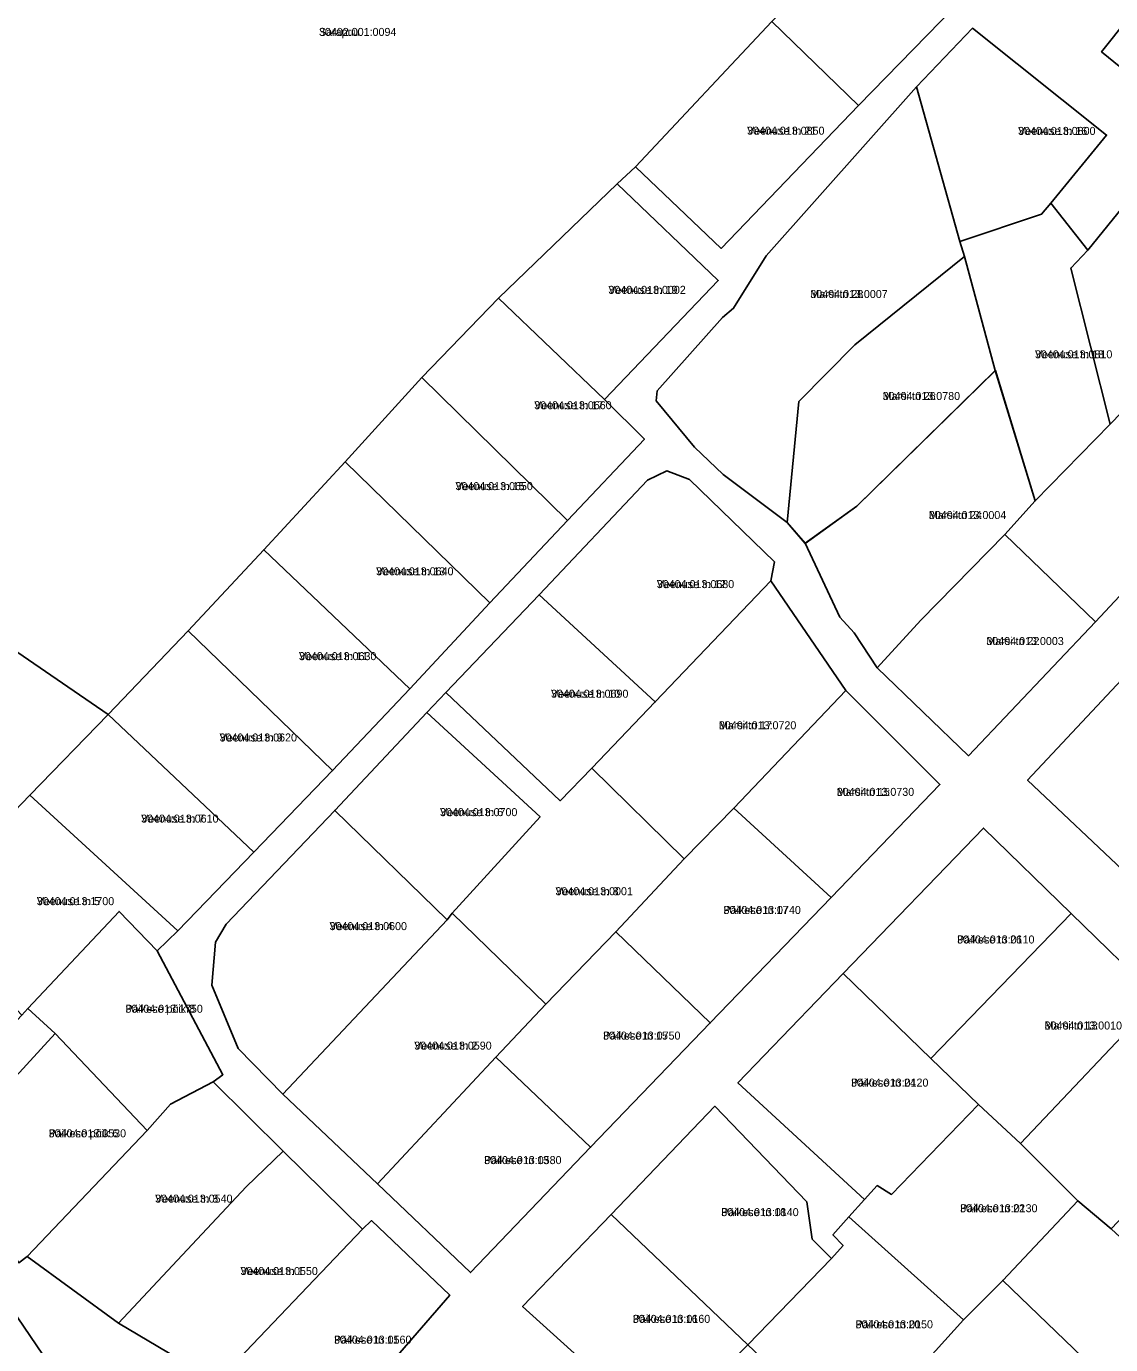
# Model space of a CAD drawing. Extents: x 542681 to 554572, y 6566489 to 6580482.
# Drawn here: x 543606.8 to 543809.9, y 6575908.9 to 6576155.9 of the extents above; entities that cross this region are included whole.
import ezdxf

# ---------------------------------------------------------------- set-up
doc = ezdxf.new("R2010")
doc.units = 0
for name, color, linetype in [('L_AADRESS', 7, 'Continuous'), ('PIIR', 7, 'Continuous'), ('TUNNUS', 7, 'Continuous')]:
    doc.layers.add(name, color=color, linetype=linetype)

msp = doc.modelspace()

# ---------------------------------------------------------------- linework, layer by layer
at = {"layer": 'PIIR'}
for points in [[(543610.08, 6576200.08), (543678.38, 6576251.99), (543771.59, 6576182.76), (543746.47, 6576156.82), (543720.94, 6576129.63), (543717.45, 6576126.42), (543695.26, 6576105.01), (543680.88, 6576090.14), (543666.51, 6576074.33), (543651.27, 6576057.86), (543637.1, 6576042.64), (543622.09, 6576026.97), (543551.63, 6576075.36)], [(543746.47, 6576156.82), (543771.59, 6576182.76), (543788.33, 6576167.45), (543762.71, 6576141.11)], [(543822.78, 6576169.45), (543851.24, 6576147.66), (543835.23, 6576129.22), (543808.25, 6576151.17)], [(543746.47, 6576156.82), (543762.71, 6576141.11), (543736.97, 6576114.33), (543720.94, 6576129.63)], [(543766.21, 6576035.75), (543783.28, 6576019.27), (543807.09, 6576044.34), (543831.37, 6576070.35), (543854.66, 6576098.47), (543838.99, 6576111.77), (543817.71, 6576128.87), (543805.64, 6576113.98), (543798.71, 6576122.83), (543809.17, 6576135.55), (543784.05, 6576155.57), (543773.55, 6576144.6), (543745.39, 6576112.95), (543739.29, 6576103.11), (543737.19, 6576101.39), (543724.96, 6576087.63), (543724.78, 6576085.78), (543731.95, 6576077.1), (543737.32, 6576071.97), (543749.35, 6576062.98), (543752.7, 6576059.07), (543759.22, 6576045.22), (543761.85, 6576042.29)], [(543773.55, 6576144.6), (543784.05, 6576155.57), (543809.17, 6576135.55), (543798.71, 6576122.83), (543796.99, 6576120.72), (543781.65, 6576115.6)], [(543724.96, 6576087.63), (543737.19, 6576101.39), (543739.29, 6576103.11), (543745.39, 6576112.95), (543773.55, 6576144.6), (543781.65, 6576115.6), (543782.54, 6576112.8), (543762.01, 6576096.24), (543751.53, 6576085.66), (543749.35, 6576062.98), (543737.32, 6576071.97), (543731.95, 6576077.1), (543724.78, 6576085.78)], [(543809.84, 6576081.36), (543802.45, 6576110.65), (543805.64, 6576113.98), (543817.71, 6576128.87), (543838.99, 6576111.77), (543814.12, 6576085.76)], [(543695.26, 6576105.01), (543717.45, 6576126.42), (543736.4, 6576108.3), (543715.11, 6576086.01)], [(543782.54, 6576112.8), (543781.65, 6576115.6), (543796.99, 6576120.72), (543798.71, 6576122.83), (543805.64, 6576113.98), (543802.45, 6576110.65), (543809.84, 6576081.36), (543795.79, 6576067.01), (543788.3, 6576091.47)], [(543752.69, 6576059.04), (543749.35, 6576062.98), (543751.53, 6576085.66), (543762.01, 6576096.24), (543782.54, 6576112.8), (543788.3, 6576091.47), (543762.37, 6576066.03)], [(543695.26, 6576105.01), (543715.11, 6576086.01), (543722.57, 6576078.55), (543708.19, 6576063.36), (543680.88, 6576090.14)], [(543788.34, 6576091.47), (543795.81, 6576067.01), (543790.13, 6576060.74), (543774.38, 6576044.65), (543766.21, 6576035.75), (543761.85, 6576042.29), (543759.22, 6576045.22), (543752.7, 6576059.07), (543762.39, 6576066.05)], [(543666.51, 6576074.33), (543680.88, 6576090.14), (543708.19, 6576063.36), (543693.61, 6576047.92)], [(543795.79, 6576067.01), (543809.84, 6576081.36), (543814.12, 6576085.76), (543831.37, 6576070.35), (543807.09, 6576044.35), (543790.12, 6576060.74)], [(543551.63, 6576075.36), (543622.09, 6576026.97), (543607.41, 6576011.85), (543587.11, 6575990.79), (543564.69, 6575967.94), (543548.38, 6575992.67), (543540.87, 6576038.52)], [(543666.51, 6576074.33), (543693.61, 6576047.92), (543678.6, 6576031.81), (543651.27, 6576057.86)], [(543672.6, 6575939.03), (543689.99, 6575922.41), (543712.5, 6575945.91), (543734.91, 6575969.18), (543757.57, 6575992.69), (543777.93, 6576013.86), (543760.33, 6576031.49), (543746.26, 6576052.05), (543746.94, 6576055.62), (543731.03, 6576071.04), (543726.81, 6576072.62), (543723.16, 6576070.89), (543702.86, 6576049.44), (543685.39, 6576031.09), (543681.82, 6576027.34), (543664.55, 6576009), (543644.22, 6575987.71), (543642.21, 6575984.35), (543641.56, 6575976.27), (543646.45, 6575964.41), (543654.81, 6575955.86)], [(543702.86, 6576049.44), (543723.16, 6576070.89), (543726.81, 6576072.62), (543731.03, 6576071.04), (543746.94, 6576055.62), (543746.26, 6576052.05), (543724.62, 6576029.34)], [(543790.13, 6576060.74), (543807.09, 6576044.34), (543783.28, 6576019.27), (543766.21, 6576035.75), (543774.38, 6576044.65)], [(543651.27, 6576057.86), (543678.6, 6576031.81), (543664.15, 6576016.49), (543637.1, 6576042.64)], [(543712.75, 6576016.93), (543724.62, 6576029.34), (543746.26, 6576052.05), (543760.33, 6576031.49), (543739.31, 6576009.43), (543730.02, 6575999.91)], [(543706.81, 6576010.83), (543685.39, 6576031.09), (543702.86, 6576049.44), (543724.62, 6576029.34), (543712.75, 6576016.93)], [(543637.1, 6576042.64), (543664.15, 6576016.49), (543649.4, 6576001.22), (543622.09, 6576026.97)], [(543794.38, 6576014.66), (543815.74, 6576037.46), (543834.84, 6576019.56), (543813.28, 6575996.79)], [(543685.39, 6576031.09), (543706.81, 6576010.83), (543712.75, 6576016.93), (543730.02, 6575999.91), (543717.22, 6575986.29), (543704.11, 6575972.68), (543686.59, 6575989.76), (543703.04, 6576007.81), (543681.82, 6576027.34)], [(543739.31, 6576009.43), (543760.33, 6576031.49), (543777.93, 6576013.86), (543757.57, 6575992.69)], [(543703.04, 6576007.81), (543686.59, 6575989.76), (543685.62, 6575988.53), (543664.55, 6576009), (543681.82, 6576027.34)], [(543607.41, 6576011.85), (543622.09, 6576026.97), (543649.4, 6576001.22), (543635.14, 6575986.48)], [(543624.15, 6575990.1), (543607.06, 6575971.92), (543605.92, 6575970.66), (543587.11, 6575990.79), (543607.41, 6576011.85), (543635.14, 6575986.48), (543631.3, 6575982.69)], [(543646.45, 6575964.41), (543641.56, 6575976.27), (543642.21, 6575984.35), (543644.22, 6575987.71), (543664.55, 6576009), (543685.62, 6575988.53), (543654.81, 6575955.86)], [(543717.22, 6575986.29), (543730.02, 6575999.91), (543739.31, 6576009.43), (543757.57, 6575992.69), (543734.91, 6575969.18)], [(543759.8, 6575978.44), (543786.1, 6576005.7), (543802.52, 6575989.67), (543776.26, 6575962.52)], [(543607.06, 6575971.92), (543624.15, 6575990.1), (543631.3, 6575982.69), (543643.62, 6575959.47), (543641.77, 6575958.14), (543633.77, 6575953.97), (543629.4, 6575949.06), (543612.18, 6575967.19)], [(543694.76, 6575962.77), (543672.6, 6575939.03), (543654.81, 6575955.86), (543685.62, 6575988.53), (543686.59, 6575989.76), (543704.11, 6575972.68)], [(543785.17, 6575953.9), (543776.26, 6575962.52), (543802.52, 6575989.67), (543818.86, 6575973.81), (543793.03, 6575946.6)], [(543694.76, 6575962.77), (543704.11, 6575972.68), (543717.22, 6575986.29), (543734.91, 6575969.18), (543712.5, 6575945.91)], [(543759.8, 6575978.44), (543776.26, 6575962.52), (543785.17, 6575953.9), (543768.9, 6575937.05), (543766.16, 6575938.72), (543763.79, 6575936.08), (543740.1, 6575957.98)], [(543803.81, 6575935.87), (543793.03, 6575946.6), (543818.86, 6575973.81), (543835.15, 6575957.43), (543828.19, 6575949.71), (543810.02, 6575930.64)], [(543629.4, 6575949.06), (543606.93, 6575925.4), (543605.37, 6575924.26), (543604.84, 6575925.1), (543601.14, 6575922.1), (543592.53, 6575940.1), (543593.32, 6575946.67), (543612.18, 6575967.19)], [(543694.76, 6575962.77), (543712.5, 6575945.91), (543689.99, 6575922.41), (543672.6, 6575939.03)], [(543633.77, 6575953.97), (543641.77, 6575958.14), (543654.88, 6575945.14), (543647.94, 6575938.5), (543624.03, 6575912.94), (543606.93, 6575925.4), (543629.4, 6575949.06)], [(543735.8, 6575953.58), (543752.98, 6575935.65), (543754.02, 6575928.65), (543757.61, 6575925.06), (543741.94, 6575908.9), (543716.35, 6575933.28)], [(543763.79, 6575936.08), (543766.16, 6575938.72), (543768.9, 6575937.05), (543785.17, 6575953.9), (543793.03, 6575946.6), (543803.81, 6575935.87), (543789.72, 6575920.93), (543782.35, 6575913.54), (543760.88, 6575932.83)], [(543640.79, 6575903.01), (543624.03, 6575912.94), (543647.94, 6575938.5), (543654.88, 6575945.14), (543669.75, 6575930.55), (543642.75, 6575902.18)], [(543803.81, 6575935.87), (543810.02, 6575930.64), (543833.47, 6575908.92), (543817.99, 6575893.76), (543789.72, 6575920.93)], [(543716.35, 6575933.28), (543741.94, 6575908.9), (543725.6, 6575892.69), (543699.76, 6575916.06)], [(543669.75, 6575930.55), (543671.42, 6575932.15), (543686.12, 6575918.2), (543659.99, 6575888.09), (543642.75, 6575902.18)], [(543741.94, 6575908.9), (543757.61, 6575925.06), (543759.79, 6575927.48), (543757.91, 6575929.5), (543760.88, 6575932.83), (543782.35, 6575913.54), (543775.35, 6575905.83), (543760.91, 6575890.98)], [(543601.14, 6575922.1), (543604.84, 6575925.1), (543605.37, 6575924.26), (543606.93, 6575925.4), (543624.03, 6575912.94), (543640.79, 6575903.01), (543624.52, 6575885.37), (543600.14, 6575921.33)], [(543782.35, 6575913.54), (543789.72, 6575920.93), (543817.99, 6575893.76), (543803.52, 6575878.89), (543775.35, 6575905.83)]]:
    msp.add_lwpolyline(points, close=True, dxfattribs=at)
for points in [[(543822.78, 6576169.45), (543808.25, 6576151.17), (543835.23, 6576129.22), (543868.39, 6576102.74), (543882.6, 6576121.55), (543906.21, 6576156.61)], [(543659.99, 6575888.09), (543686.12, 6575918.2), (543671.42, 6575932.15), (543669.75, 6575930.55), (543654.88, 6575945.14), (543641.77, 6575958.14), (543643.62, 6575959.47), (543631.3, 6575982.69), (543635.14, 6575986.48), (543649.4, 6576001.22), (543664.15, 6576016.49), (543678.6, 6576031.81), (543693.61, 6576047.92), (543708.19, 6576063.36), (543722.57, 6576078.55), (543715.11, 6576086.01), (543736.4, 6576108.3), (543717.45, 6576126.42), (543720.94, 6576129.63), (543736.97, 6576114.33), (543762.71, 6576141.11), (543788.33, 6576167.45)], [(543815.74, 6576037.46), (543794.38, 6576014.66), (543813.28, 6575996.79)], [(543817.99, 6575893.76), (543833.47, 6575908.92), (543851.52, 6575929.2), (543828.19, 6575949.71), (543835.15, 6575957.43), (543818.86, 6575973.81), (543802.52, 6575989.67), (543786.1, 6576005.7), (543759.8, 6575978.44), (543740.1, 6575957.98), (543763.79, 6575936.08), (543760.88, 6575932.83), (543757.91, 6575929.5), (543759.79, 6575927.48), (543757.61, 6575925.06), (543754.02, 6575928.65), (543752.98, 6575935.65), (543735.8, 6575953.58), (543716.35, 6575933.28), (543699.76, 6575916.06), (543725.6, 6575892.69)], [(543601.06, 6575907.27), (543588.12, 6575936.11), (543583.17, 6575946.33), (543605.92, 6575970.66), (543607.06, 6575971.92), (543612.18, 6575967.19), (543593.32, 6575946.67), (543592.53, 6575940.1), (543601.14, 6575922.1), (543600.14, 6575921.33), (543624.52, 6575885.37)]]:
    msp.add_lwpolyline(points, dxfattribs=at)

# ---------------------------------------------------------------- texts
at = {"layer": 'L_AADRESS'}
for s, p in [('Sarapuu', (543661.61, 6576154.14)), ('Veenuse tn 21', (543741.82, 6576135.63)), ('Veenuse tn 16', (543792.6, 6576135.59)), ('Veenuse tn 19', (543715.83, 6576105.81)), ('Marsi tn 28', (543753.66, 6576105.03)), ('Veenuse tn 18', (543795.75, 6576093.73)), ('Marsi tn 26', (543767.22, 6576085.92)), ('Veenuse tn 17', (543701.94, 6576084.19)), ('Veenuse tn 15', (543687.18, 6576069.03)), ('Marsi tn 24', (543775.87, 6576063.61)), ('Veenuse tn 13', (543672.31, 6576053.07)), ('Veenuse tn 12', (543724.9, 6576050.67)), ('Marsi tn 22', (543786.65, 6576040)), ('Veenuse tn 11', (543657.86, 6576037.17)), ('Veenuse tn 10', (543705.08, 6576030.13)), ('Marsi tn 17', (543736.54, 6576024.22)), ('Veenuse tn 9', (543642.98, 6576021.93)), ('Marsi tn 15', (543758.62, 6576011.74)), ('Veenuse tn 7', (543628.29, 6576006.73)), ('Veenuse tn 6', (543684.28, 6576007.94)), ('Veenuse tn 5', (543608.74, 6575991.26)), ('Veenuse tn 8', (543705.92, 6575993.12)), ('Päikese tn 17', (543737.39, 6575989.61)), ('Veenuse tn 4', (543663.59, 6575986.58)), ('Päikese tn 26', (543781.16, 6575984.08)), ('Päikese põik 8', (543625.34, 6575971.1)), ('Marsi tn 13', (543797.56, 6575967.96)), ('Veenuse tn 2', (543679.46, 6575964.19)), ('Päikese tn 15', (543714.83, 6575966.07)), ('Päikese tn 24', (543761.29, 6575957.26)), ('Päikese põik 6', (543610.96, 6575947.76)), ('Päikese tn 13', (543692.55, 6575942.74)), ('Veenuse tn 3', (543630.91, 6575935.52)), ('Päikese tn 18', (543736.98, 6575932.99)), ('Päikese tn 22', (543781.73, 6575933.72)), ('Veenuse tn 1', (543646.89, 6575921.95)), ('Päikese tn 16', (543720.41, 6575912.99)), ('Päikese tn 20', (543762.14, 6575911.97)), ('Päikese tn 11', (543664.43, 6575909.09))]:
    msp.add_text(s, height=1.5, dxfattribs=at).set_placement(p)
at = {"layer": 'TUNNUS'}
for s, p in [('30402:001:0094', (543661.61, 6576154.14)), ('30404:013:0850', (543741.82, 6576135.63)), ('30404:013:0800', (543792.6, 6576135.59)), ('30404:013:0002', (543715.83, 6576105.81)), ('30404:013:0007', (543753.66, 6576105.03)), ('30404:013:0810', (543795.75, 6576093.73)), ('30404:013:0780', (543767.22, 6576085.92)), ('30404:013:0660', (543701.94, 6576084.19)), ('30404:013:0650', (543687.18, 6576069.03)), ('30404:013:0004', (543775.87, 6576063.61)), ('30404:013:0640', (543672.31, 6576053.07)), ('30404:013:0680', (543724.9, 6576050.67)), ('30404:013:0003', (543786.65, 6576040)), ('30404:013:0630', (543657.86, 6576037.17)), ('30404:013:0690', (543705.08, 6576030.13)), ('30404:013:0720', (543736.54, 6576024.22)), ('30404:013:0620', (543642.98, 6576021.93)), ('30404:013:0730', (543758.62, 6576011.74)), ('30404:013:0610', (543628.29, 6576006.73)), ('30404:013:0700', (543684.28, 6576007.94)), ('30404:013:1700', (543608.74, 6575991.26)), ('30404:013:0001', (543705.92, 6575993.12)), ('30404:013:0740', (543737.39, 6575989.61)), ('30404:013:0600', (543663.59, 6575986.58)), ('30404:013:0110', (543781.16, 6575984.08)), ('30404:013:1750', (543625.34, 6575971.1)), ('30404:013:0010', (543797.56, 6575967.96)), ('30404:013:0590', (543679.46, 6575964.19)), ('30404:013:0750', (543714.83, 6575966.07)), ('30404:013:0120', (543761.29, 6575957.26)), ('30404:013:0530', (543610.96, 6575947.76)), ('30404:013:0580', (543692.55, 6575942.74)), ('30404:013:0540', (543630.91, 6575935.52)), ('30404:013:0140', (543736.98, 6575932.99)), ('30404:013:0130', (543781.73, 6575933.72)), ('30404:013:0550', (543646.89, 6575921.95)), ('30404:013:0160', (543720.41, 6575912.99)), ('30404:013:0150', (543762.14, 6575911.97)), ('30404:013:0560', (543664.43, 6575909.09))]:
    msp.add_text(s, height=1.5, dxfattribs=at).set_placement(p)

doc.saveas('drawing.dxf')
